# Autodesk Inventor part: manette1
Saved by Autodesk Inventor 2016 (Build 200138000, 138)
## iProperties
Created: 2013-10
Part Number: manette1
Material: solidworks materials|ABS
Document SubType Name: Modeling
Designer: Bruno
Density: 1.02 g/cm^3
Appearance: 255,255,2551
Author: Bruno
Sending System: SolidWorks 2013
Last Author: christophe
Last Saved: 2014-02-15
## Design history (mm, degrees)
feature "Cut-Revolve2"
node "Solide1"
